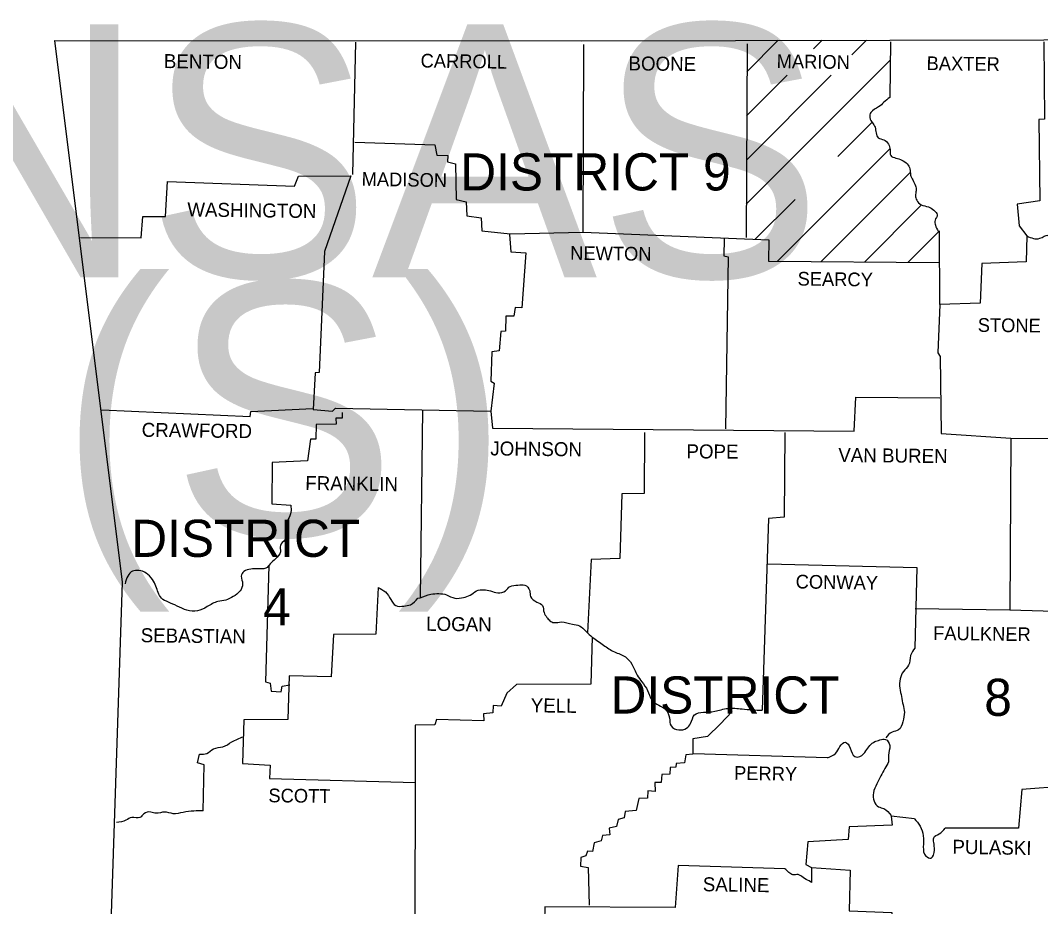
# Model space of a CAD drawing. Extents: x 1370130 to 1380143, y 377636 to 380256.
# Drawn here: x 1379430.8 to 1379759.2, y 379208.7 to 379493.7 of the extents above; entities that cross this region are included whole.
import ezdxf

# ---------------------------------------------------------------- set-up
doc = ezdxf.new("R2010")
doc.units = 0
doc.layers.add('R_Draft', color=7, linetype='Continuous')

msp = doc.modelspace()

# ---------------------------------------------------------------- linework, layer by layer
at = {"layer": 'R_Draft'}
for p, q in [((1379664.66, 379477.21), (1379674.77, 379487.32)), ((1379686.11, 379484.53), (1379688.94, 379487.35)), ((1379698.4, 379482.67), (1379703.11, 379487.38)), ((1379664.44, 379434.57), (1379710.77, 379480.9)), ((1379664.51, 379448.78), (1379691.8, 379476.07)), ((1379664.58, 379463), (1379677.67, 379476.08)), ((1379693.93, 379449.92), (1379704.97, 379460.95)), ((1379674.51, 379416.28), (1379710.66, 379452.43)), ((1379688.55, 379416.17), (1379717.21, 379444.83)), ((1379667.32, 379423.3), (1379680.16, 379436.15)), ((1379702.58, 379416.06), (1379720.87, 379434.35)), ((1379716.62, 379415.96), (1379726.68, 379426.02))]:
    msp.add_line(p, q, dxfattribs=at)
for points in [[(1379441.86, 379487.29), (1379611.43, 379487.19), (1379760.24, 379487.5), (1379935.79, 379490.23), (1380017.16, 379492.12)], [(1379441.86, 379487.29), (1379463.57, 379313.01), (1379454.13, 379028.51)], [(1379538.65, 379486.67), (1379537.71, 379444.2)], [(1379710.84, 379486.88), (1379710.63, 379468.94)], [(1379760.24, 379486.88), (1379760.45, 379461.92), (1379758.66, 379461.81), (1379758.98, 379435.7), (1379751.64, 379434.65), (1379752.27, 379427.63), (1379754.78, 379424.38), (1379754.57, 379416.09), (1379740.31, 379415.57), (1379739.79, 379402.77), (1379726.78, 379402.35), (1379726.15, 379386.83), (1379726.89, 379385.58), (1379727.2, 379360.83), (1379749.64, 379359.36), (1379749.33, 379304.1), (1379767.16, 379303.57), (1379767.16, 379247.36), (1379753.11, 379246.31), (1379752.06, 379233.94), (1379728.46, 379233.84)], [(1379538.44, 379454.58), (1379564.24, 379453.74), (1379564.87, 379450.38), (1379568.43, 379450.28), (1379568.33, 379448.18), (1379570.85, 379447.55), (1379571.05, 379436.12), (1379574.31, 379435.39), (1379574.52, 379430.88), (1379579.13, 379430.25), (1379579.34, 379426.05), (1379588.46, 379425.11), (1379611.95, 379425.63), (1379612.16, 379485.93)], [(1379664.7, 379486.14), (1379664.39, 379423.85)], [(1379450.14, 379423.85), (1379469.75, 379423.75), (1379470.28, 379430.67), (1379477.51, 379430.67), (1379478.14, 379441.89), (1379519.04, 379440.42), (1379520.3, 379443.57), (1379537.18, 379443.67), (1379528.69, 379419.34), (1379527.01, 379380.44), (1379525.75, 379380.33), (1379525.12, 379368.59), (1379531.31, 379368.06), (1379532.25, 379369.01), (1379582.28, 379368.06), (1379582.8, 379362.51)], [(1379588.25, 379424.9), (1379588.67, 379419.24), (1379593.5, 379418.92), (1379592.24, 379401.31), (1379590.04, 379401.41), (1379589.62, 379398.58), (1379587.1, 379398.58), (1379586.99, 379393.76), (1379585.42, 379393.65), (1379584.9, 379387.46), (1379582.59, 379387.15), (1379582.28, 379377.71), (1379583.32, 379376.98), (1379582.28, 379368.06)], [(1379611.95, 379425.63), (1379671.73, 379423.12), (1379671.62, 379416.3), (1379726.47, 379415.88)], [(1379726.78, 379402.35), (1379726.68, 379425.95)], [(1379657.36, 379423.43), (1379657.26, 379417.98), (1379658.62, 379417.66), (1379657.78, 379362.3)], [(1379582.8, 379362.51), (1379699.2, 379361.56), (1379699.73, 379372.57), (1379726.78, 379372.26)], [(1379457.06, 379368.48), (1379504.78, 379366.28), (1379504.99, 379367.96), (1379524.91, 379368.9)], [(1379560.25, 379368.48), (1379559.52, 379307.98)], [(1379534.35, 379367.64), (1379534.35, 379365.76), (1379532.36, 379365.76), (1379532.46, 379363.87), (1379526.07, 379363.76), (1379525.96, 379359.04), (1379524.18, 379359.04), (1379523.23, 379352.02), (1379511.91, 379351.49), (1379511.8, 379338.18), (1379517.89, 379337.76)], [(1379631.7, 379361.18), (1379631.59, 379341.57), (1379624.36, 379341.46), (1379623.73, 379320.59), (1379614.5, 379320.28), (1379613.36, 379296.75)], [(1379676.87, 379361.14), (1379676.66, 379333.88), (1379671.62, 379333.46), (1379669.63, 379271.8)], [(1379749.64, 379359.36), (1379803.55, 379359.04), (1379808.16, 379361.25), (1379807.85, 379320.24), (1379804.7, 379318.88), (1379801.87, 379316.47), (1379800.93, 379315.53), (1379800.82, 379303.78), (1379766.53, 379303.78)], [(1379510.79, 379318.34), (1379509.71, 379280.92), (1379511.28, 379280.5), (1379511.59, 379277.98), (1379514.74, 379277.77), (1379515.06, 379279.56), (1379517.57, 379279.98)], [(1379671.41, 379318.88), (1379719.34, 379317.73), (1379718.71, 379291.83)], [(1379545.99, 379311.33), (1379545.26, 379296.34), (1379531.62, 379296.23), (1379530.89, 379282.6), (1379517.36, 379282.91), (1379516.94, 379268.86), (1379502.79, 379268.76), (1379502.37, 379254.7), (1379511.28, 379254.18), (1379510.97, 379249.88), (1379557.88, 379248.58)], [(1379558.79, 379307.87), (1379559.52, 379307.98)], [(1379718.81, 379304.51), (1379749.33, 379304.1)], [(1379614.89, 379295.29), (1379614.47, 379280.19), (1379590.56, 379280.08), (1379587.41, 379277.35), (1379585.63, 379273.16), (1379583.01, 379273.37), (1379582.9, 379270.96), (1379579.86, 379270.64), (1379579.97, 379268.44), (1379564.76, 379268.86), (1379564.24, 379267.18), (1379557.95, 379266.97), (1379557.88, 379248.58)], [(1379659.88, 379271.38), (1379656.1, 379267.29), (1379652.01, 379263.41), (1379647.29, 379262.67), (1379647.29, 379257.74), (1379644.99, 379257.43), (1379644.57, 379254.91), (1379641.95, 379254.7), (1379641.74, 379253.55), (1379639.95, 379253.45), (1379639.85, 379251.24), (1379637.33, 379251.14), (1379637.12, 379248.62), (1379635.02, 379248.62), (1379635.13, 379245.69), (1379632.82, 379245.9), (1379632.72, 379243.59), (1379629.89, 379243.38), (1379629.05, 379239.6), (1379625.48, 379239.29), (1379625.17, 379237.19), (1379623.28, 379236.67), (1379622.75, 379234.46), (1379620.34, 379233.94), (1379620.55, 379231.74), (1379618.14, 379231.53), (1379617.72, 379229.85), (1379615.52, 379229.22), (1379614.99, 379226.39), (1379613.32, 379226.5), (1379612.79, 379225.03), (1379611.22, 379224.5), (1379611.11, 379221.67), (1379613.53, 379221.25), (1379613.95, 379209.09)], [(1379489.68, 379239.5), (1379489.99, 379254.28), (1379487.89, 379254.91), (1379488.52, 379257.74)], [(1379690.6, 379256.49), (1379647.4, 379257.85)], [(1379557.88, 379248.58), (1379557.74, 379205.63), (1379552.49, 379205.52), (1379552.91, 379202.38), (1379547.88, 379202.48), (1379547.77, 379200.17), (1379542.85, 379200.17), (1379542.95, 379198.5), (1379535.61, 379198.29), (1379535.5, 379191.89), (1379528.37, 379192.52), (1379527.22, 379140.92), (1379486.85, 379141.03), (1379485.9, 379129.08), (1379487.37, 379128.03), (1379487.27, 379114.6), (1379458.64, 379115.86)], [(1379718.6, 379236.88), (1379711.05, 379237.72), (1379711.37, 379234.88), (1379697.63, 379234.36), (1379697.21, 379230.27), (1379684.31, 379229.54), (1379683.58, 379222.2), (1379685.47, 379221.25), (1379685.47, 379216.43)], [(1379676.87, 379220.83), (1379642.57, 379221.88), (1379641.63, 379208.35), (1379599.68, 379208.56), (1379599.51, 379204.03)], [(1379685.47, 379221.19), (1379697.94, 379220.41), (1379697.53, 379207.3), (1379711.26, 379206.78), (1379711.47, 379195.35), (1379717.97, 379194.83), (1379717.97, 379192.83), (1379724.06, 379192.41), (1379724.27, 379185.07), (1379738.11, 379185.07), (1379738.53, 379177.84), (1379751.32, 379177.21), (1379751.22, 379163.58)], [(1379685.47, 379216.43), (1379684.73, 379216.95)]]:
    msp.add_lwpolyline(points, dxfattribs=at)
for points in [[(1379710.63, 379468.94), (1379708.75, 379467.37), (1379707.07, 379465.9), (1379704.55, 379464.12), (1379704.24, 379462.44), (1379705.08, 379460.76), (1379705.91, 379459.4), (1379706.23, 379457.51), (1379706.96, 379455.94), (1379708.75, 379455.31), (1379710.21, 379453.95), (1379710.74, 379452.06), (1379710.95, 379450.28), (1379712.63, 379449.44), (1379714.51, 379448.81), (1379716.3, 379447.55), (1379717.14, 379445.98), (1379717.35, 379443.99), (1379718.08, 379442.41), (1379718.92, 379440.53), (1379719.13, 379438.95), (1379718.92, 379437.38), (1379719.34, 379435.91), (1379720.7, 379434.44), (1379723.11, 379433.71), (1379724.79, 379432.66), (1379725.94, 379431.19), (1379725.21, 379429.41), (1379725.32, 379427.84), (1379726.26, 379425.95)], [(1379754.78, 379424.38), (1379758.98, 379423.64), (1379761.49, 379424.59), (1379763.28, 379421.86), (1379764.22, 379419.76), (1379765.79, 379416.72), (1379768.31, 379415.78), (1379770.2, 379414.1), (1379770.2, 379412.32), (1379768.52, 379410.64), (1379767.26, 379408.96), (1379767.68, 379406.97), (1379768.1, 379404.24), (1379768.1, 379401.62), (1379767.47, 379399.21), (1379766.95, 379397.01), (1379767.47, 379395.12), (1379769.46, 379395.43), (1379771.56, 379397.01), (1379773.76, 379397.01), (1379775.86, 379395.85), (1379778.06, 379393.86), (1379780.27, 379394.28), (1379782.05, 379394.8), (1379784.57, 379395.54), (1379786.35, 379394.59), (1379787.92, 379393.34), (1379789.81, 379391.34), (1379791.59, 379390.08), (1379793.9, 379388.93), (1379796.73, 379388.2), (1379799.35, 379386.41), (1379799.77, 379383.37), (1379799.67, 379380.75), (1379799.46, 379377.5), (1379799.25, 379373.94), (1379799.56, 379370.47), (1379800.72, 379368.17), (1379802.18, 379365.44), (1379802.6, 379362.92), (1379802.5, 379358.94)], [(1379517.89, 379337.76), (1379517.89, 379335.55), (1379517.05, 379333.25), (1379516.52, 379331.26), (1379516.84, 379328.63), (1379515.89, 379326.54), (1379514.53, 379324.86), (1379514.53, 379322.76), (1379512.96, 379320.56), (1379511.28, 379318.88), (1379509.81, 379317.52), (1379507.19, 379317.31), (1379504.99, 379317.2), (1379502.79, 379316.47), (1379501.95, 379314.9), (1379502.37, 379312.48), (1379501.53, 379310.18), (1379499.33, 379308.39), (1379496.91, 379307.24), (1379494.4, 379306.82), (1379490.94, 379305.14), (1379487.79, 379303.78), (1379484.43, 379303.99), (1379481.29, 379305.35), (1379478.46, 379306.61), (1379476.25, 379307.87), (1379474.47, 379311.75), (1379473.32, 379313.85), (1379471.33, 379315.95), (1379468.91, 379316.78), (1379466.92, 379316.57), (1379464.51, 379312.48)], [(1379545.99, 379311.33), (1379548.3, 379309.86), (1379550.08, 379307.45), (1379551.65, 379305.46), (1379554.28, 379305.35), (1379556.37, 379305.77), (1379558.79, 379307.87)], [(1379559.52, 379307.98), (1379562.98, 379309.13), (1379565.5, 379309.34), (1379568.01, 379308.92), (1379570.64, 379307.87), (1379573.47, 379308.08), (1379575.56, 379308.81), (1379577.66, 379310.18), (1379579.97, 379310.6), (1379582.17, 379310.18), (1379584.48, 379309.55), (1379586.99, 379310.28), (1379588.46, 379311.65), (1379590.98, 379312.07), (1379593.18, 379312.07), (1379594.75, 379310.28), (1379595.07, 379308.39), (1379597.06, 379306.61), (1379598.84, 379305.46), (1379599.37, 379303.26), (1379600.31, 379301.68), (1379601.26, 379300.63), (1379602.62, 379300.01), (1379604.93, 379300.22), (1379608.49, 379299.48), (1379610.8, 379298.96), (1379612.9, 379297.17), (1379614.89, 379295.29)], [(1379614.89, 379295.29), (1379618.56, 379292.77), (1379622.02, 379290.57), (1379625.59, 379288.99), (1379627.58, 379286.69), (1379629.36, 379283.12), (1379630.83, 379280.92), (1379632.72, 379278.19), (1379634.08, 379275.15), (1379636.28, 379273.47), (1379638.59, 379272.01), (1379639.74, 379269.38), (1379640.27, 379266.76), (1379642.78, 379265.5), (1379645.2, 379266.03), (1379646.56, 379267.6), (1379647.82, 379270.33), (1379650.65, 379271.17), (1379654.32, 379271.48), (1379658.51, 379272.43), (1379663.13, 379272.22), (1379669.63, 379271.8)], [(1379718.71, 379291.83), (1379717.35, 379289.41), (1379716.72, 379286.27), (1379715.04, 379284.28), (1379713.99, 379281.97), (1379713.88, 379278.93), (1379714.41, 379276.2), (1379714.93, 379273.58), (1379715.35, 379271.17), (1379714.83, 379268.13), (1379713.47, 379265.5), (1379711.37, 379264.77), (1379709.38, 379262.99)], [(1379488.52, 379257.74), (1379490.83, 379257.95), (1379493.03, 379259.42), (1379495.97, 379260.05), (1379498.91, 379261.62), (1379502.58, 379263.3)], [(1379690.6, 379256.49), (1379693.23, 379257.95), (1379694.59, 379260.16), (1379696.27, 379261.52), (1379697.94, 379259.63), (1379699.41, 379256.91), (1379700.99, 379256.91), (1379702.98, 379258.79), (1379704.24, 379260.47), (1379705.81, 379261.73), (1379707.49, 379262.25), (1379709.27, 379262.46), (1379710.63, 379260.47), (1379710.21, 379257.33), (1379710.21, 379255.23), (1379709.06, 379253.03), (1379707.8, 379250.72), (1379706.44, 379248.1), (1379705.39, 379245.27), (1379705.6, 379242.54), (1379707.07, 379240.76), (1379708.75, 379240.23), (1379711.05, 379237.93)], [(1379489.68, 379239.5), (1379486.64, 379239.39), (1379483.18, 379238.97), (1379480.03, 379238.55), (1379477.2, 379239.08), (1379474.58, 379238.66), (1379472.79, 379239.08), (1379470.59, 379238.55), (1379469.33, 379237.3), (1379466.71, 379237.3), (1379464.82, 379236.46), (1379461.78, 379235.72)], [(1379718.6, 379236.88), (1379720.39, 379234.57), (1379721.44, 379231.42), (1379721.44, 379227.86), (1379722.27, 379224.92), (1379723.95, 379224.29), (1379725, 379226.81), (1379724.79, 379229.33), (1379724.79, 379230.79), (1379726.57, 379232.05), (1379728.46, 379233.84)], [(1379684.73, 379216.95), (1379682.74, 379218), (1379681.17, 379218.94), (1379679.49, 379218.84), (1379678.12, 379219.68), (1379676.87, 379220.83)]]:
    msp.add_spline(points, degree=3, dxfattribs=at)

# ---------------------------------------------------------------- texts
for s, height, p in [('MISSOURI & NORTHERN ARKANSAS', 81.4158, (1377777.56, 379411.09)), ('DISTRICT 9', 11.955, (1379572.4, 379439.01)), ('RR STR. & APPRS. (SUMMIT) (S)', 81.4158, (1377912.82, 379328.04)), ('DISTRICT', 11.955, (1379466.51, 379321.15)), ('4', 11.95, (1379508.98, 379299.13)), ('DISTRICT', 11.955, (1379620.76, 379270.75)), ('8', 11.95, (1379741.05, 379270.01))]:
    msp.add_text(s, height=height, dxfattribs=at).set_placement(p)
for s, height, rotation, p in [('BENTON', 4.51, 359.2527, (1379476.99, 379478.38)), ('CARROLL', 4.405, 359.1481, (1379559.62, 379478.59)), ('BOONE', 4.51, 359.4001, (1379626.53, 379477.65)), ('MARION', 4.405, 359.1854, (1379674.22, 379478.41)), ('BAXTER', 4.405, 359.256, (1379722.48, 379477.75)), ('MADISON', 4.405, 359.0906, (1379540.64, 379440.53)), ('WASHINGTON', 4.509, 359.232, (1379484.54, 379430.67)), ('NEWTON', 4.405, 359.2717, (1379607.76, 379416.72)), ('SEARCY', 4.404, 359.2527, (1379680.96, 379408.44)), ('STONE', 4.404, 359.4001, (1379738.95, 379393.55)), ('CRAWFORD', 4.509, 359.2771, (1379469.86, 379359.78)), ('JOHNSON', 4.51, 359.3514, (1379582.07, 379353.8)), ('POPE', 4.51, 359.6155, (1379645.2, 379352.86)), ('VAN BUREN', 4.51, 359.3508, (1379694.06, 379351.7)), ('FRANKLIN', 4.51, 359.1816, (1379522.5, 379342.69)), ('CONWAY', 4.404, 359.0372, (1379680.33, 379311.02)), ('LOGAN', 4.51, 359.3969, (1379561.41, 379297.38)), ('SEBASTIAN', 4.509, 359.2816, (1379469.54, 379293.71)), ('FAULKNER', 4.405, 359.2486, (1379724.58, 379294.45)), ('YELL', 4.51, 359.1987, (1379595.07, 379271.17)), ('PERRY', 4.405, 359.0858, (1379660.51, 379249.46)), ('SCOTT', 4.405, 359.4063, (1379510.65, 379242.22)), ('PULASKI', 4.51, 359.0531, (1379730.77, 379225.66)), ('SALINE', 4.51, 359.1492, (1379650.44, 379213.6))]:
    msp.add_text(s, height=height, rotation=rotation, dxfattribs=at).set_placement(p)

doc.saveas('drawing.dxf')
